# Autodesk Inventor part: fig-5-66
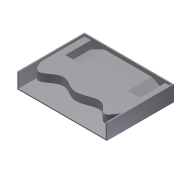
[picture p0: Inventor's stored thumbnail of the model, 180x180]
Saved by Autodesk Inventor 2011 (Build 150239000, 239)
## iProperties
Created: 2004-05
Part Number: fig-5-66
Document SubType Name: Modeling
Designer: CADCIM Technologies
Manufacturer: Standard
Standards Organization: Custom
Density: 1 g/cm^3
Author: CADCIM Technologies
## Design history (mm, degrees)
sketch "Sketch1"
  geometry: L1 (-40, -30)-(40, -30); L2 (40, -30)-(40, 30); L3 (40, 30)-(-40, 30); L4 (-40, 30)-(-40, -30); 1 further point
  constraints: 8 end point, 2 parallel, 1 horizontal, 1 perpendicular, 1 other
  dimensions: "d0" = 80 distance of L1.start L1.end; "d1" = 60 distance of L3.end L1.start; "d2" = 30 distance from line of point (0, 0) L1; "d3" = 40 distance from line of point (0, 0) L4
extrude "Extrusion1" new body sketch "Sketch1" distance "d4" = 14; taper "d5" = 0 deg
shell "Shell1" dims "d6" = 1
workplane "Work Plane1"
sketch "Sketch2"
  geometry: L1 (78, -13)-(78, -11.813); L2 (0, -11.813)-(0, -13); L3 (0, -13)-(78, -13); L4 (0, -11.813)-(17.826, -3.295); L5 (17.826, -3.295)-(60.174, -3.295); L6 (60.174, -3.295)-(78, -11.813); L7 (79, -13.795)-(78, -13.795); L8 (78, 0)-(78, -13) reference; L9 (0, -13)-(0, 0) reference; L10 (78, -13)-(0, -13) reference
  constraints: 14 end point, 3 collinear, 2 equal length, 2 vertical, 1 horizontal alignment, 1 parallel, 1 point on line
extrude "Extrusion2" join sketch "Sketch2" stored distance "d8" = 14; taper "d9" = 0 deg
workplane "Work Plane2"
sketch "Sketch3"
  geometry: 7 further points
  constraints: 7 other
extrude "Extrusion7" join sketch "Sketch3" distance "d27" = 7; taper "d28" = 0 deg
body "Solid1"
other parameters: "d7" = 23, "d18" = 4, "d29" = 7
